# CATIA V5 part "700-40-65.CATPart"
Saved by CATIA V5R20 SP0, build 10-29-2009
Part number: 700-40-65
Revision: ANY
Definition: UNKNOWN
Nomenclature: 700-40-65
Source: Unknown
Bounding box of the stored display mesh (mm): x -20 to 20, y 0 to 65, z -20 to 20
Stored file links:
  C:\Users\Utente\Desktop\IO LAVORO\3D X SITO CF\X SITO\700\700-40-65.CATPart
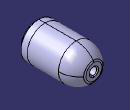
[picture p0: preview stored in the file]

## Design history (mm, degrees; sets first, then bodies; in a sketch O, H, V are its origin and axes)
Body1 "Smusso1" (main body)
  Solid1: solid without history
